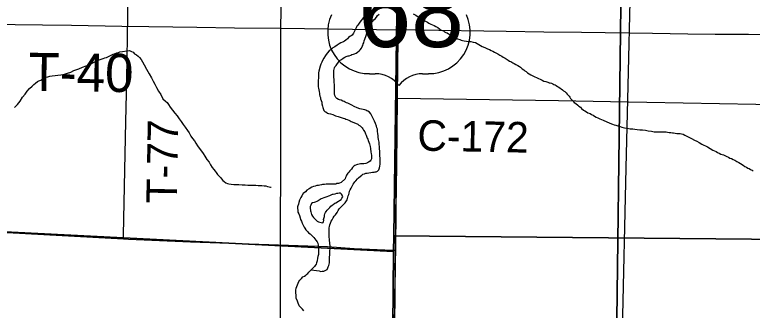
# Model space of a CAD drawing. Extents: x 0 to 68, y 0 to 52.9.
# Drawn here: x 43.122 to 44.57, y 34.125 to 34.705 of the extents above; entities that cross this region are included whole.
import ezdxf

# ---------------------------------------------------------------- set-up
doc = ezdxf.new("R2010")
doc.units = 0
for name, color, linetype in [('Default', 7, 'Continuous'), ('GM_X_County_Road', 7, 'Continuous'), ('GM_X_County_Road_Text', 7, 'Continuous'), ('GM_X_Minor_River', 7, 'Continuous'), ('GM_X_Township', 7, 'Continuous'), ('GM_X_Township_Road', 7, 'Continuous'), ('GM_X_Township_Road_Text', 7, 'Continuous')]:
    doc.layers.add(name, color=color, linetype=linetype)

msp = doc.modelspace()

# ---------------------------------------------------------------- linework, layer by layer
at = {"layer": 'Default'}
for p, q in [((43.8182, 34.5896), (43.8298, 34.5896)), ((43.9227, 34.5896), (43.9343, 34.5896))]:
    msp.add_line(p, q, dxfattribs=at)
for points in [[(43.6416, 32.7683), (43.6433, 34.0176), (43.6445, 34.6783), (43.656, 35.3485), (43.6679, 36.0083), (43.677, 36.4459), (43.686, 36.8454), (43.6904, 37.0468), (43.6959, 37.2899), (43.6976, 37.3155), (43.7023, 37.357), (43.7061, 37.3835), (43.7187, 37.4504), (43.791, 37.8727), (43.7942, 37.8955), (43.7959, 37.9156), (43.7976, 37.9355), (43.7985, 37.9597), (43.7994, 37.991), (43.8015, 38.1232), (43.8073, 38.5411), (43.8097, 38.7192)], [(44.3156, 34.0851), (44.3228, 34.4048), (44.3263, 34.5659), (44.3308, 34.7604), (44.3321, 34.7808), (44.3359, 34.8141), (44.3389, 34.8352), (44.3489, 34.8887), (44.4068, 35.2266), (44.4093, 35.2448), (44.4107, 35.261), (44.4121, 35.2768), (44.4128, 35.2962), (44.4135, 35.3212), (44.4152, 35.427), (44.4199, 35.7613)], [(43.8675, 34.0362), (43.8697, 34.2199), (43.87, 34.2429), (43.871, 34.3249), (43.8721, 34.4102), (43.8734, 34.5417), (43.874, 34.6063), (43.8751, 34.708), (43.8755, 34.7358)]]:
    msp.add_lwpolyline(points, dxfattribs=at)
for points in [[(43.1026, 35.3466), (43.6933, 35.3509), (44.3202, 35.3382), (44.3032, 34.0046), (43.0873, 34.0306), (43.1022, 35.3161)], [(44.3202, 35.3382), (45.6672, 35.3023), (45.6451, 33.9748), (44.3032, 34.0046)], [(42.821, 35.3089), (43.8802, 35.2907), (43.8665, 34.2714), (43.8657, 34.2406), (42.8041, 34.2941)], [(43.8802, 35.2907), (44.9023, 35.2801), (44.8493, 34.2618), (43.8665, 34.2714)], [(42.8041, 34.2941), (43.8657, 34.2406), (43.8561, 33.2057), (43.8558, 33.1813), (42.7855, 33.2374)], [(43.8665, 34.2714), (44.8493, 34.2618), (44.8302, 33.199), (44.3286, 33.2092), (43.8561, 33.2057), (43.8657, 34.2406)]]:
    msp.add_lwpolyline(points, close=True, dxfattribs=at)
for centre, radius, start, end in [((43.8173, 34.6709), 0.0812, 154.8319, 270.6383), ((43.9352, 34.6709), 0.0812, 269.3617, 25.1681), ((43.8298, 34.5316), 0.058, 36.8699, 90), ((43.9227, 34.5316), 0.058, 90, 143.1301)]:
    msp.add_arc(centre, radius, start, end, dxfattribs=at)
at = {"layer": 'GM_X_County_Road'}
for points in [[(43.8734, 34.5417), (44.1895, 34.5367), (44.3255, 34.5342)], [(44.3255, 34.5342), (44.3272, 34.5341), (44.363, 34.5335), (44.6485, 34.5287), (44.9175, 34.5237), (45.1209, 34.519), (45.1669, 34.5181), (45.3604, 34.5135), (45.4008, 34.5128)]]:
    msp.add_lwpolyline(points, dxfattribs=at)
at = {"layer": 'GM_X_Minor_River'}
for points in [[(43.7885, 34.5252), (43.7837, 34.5277), (43.7809, 34.5289), (43.7785, 34.5302), (43.7757, 34.5314), (43.7733, 34.5326), (43.7709, 34.5339), (43.7685, 34.5351), (43.7661, 34.5359), (43.7625, 34.5376), (43.7592, 34.5384), (43.7572, 34.5392), (43.7544, 34.5409), (43.7521, 34.5429), (43.7501, 34.5465), (43.7497, 34.5502), (43.7497, 34.5522), (43.7498, 34.5554), (43.7494, 34.5574), (43.7494, 34.5602), (43.7494, 34.5638), (43.7495, 34.5678), (43.7491, 34.5727), (43.7488, 34.5759), (43.7488, 34.5787), (43.7484, 34.5819), (43.7484, 34.5843), (43.7481, 34.5863), (43.7481, 34.5884), (43.7485, 34.5908), (43.7481, 34.5932), (43.7486, 34.5956), (43.749, 34.5988), (43.7498, 34.6012), (43.7506, 34.6032), (43.7527, 34.606), (43.7588, 34.6144), (43.7608, 34.616), (43.7636, 34.6175), (43.7669, 34.6199), (43.7701, 34.6219), (43.7725, 34.6235), (43.7766, 34.6246), (43.7786, 34.6246), (43.7814, 34.6258), (43.7838, 34.627), (43.7871, 34.6281), (43.7891, 34.6289), (43.7919, 34.6301), (43.7951, 34.6321), (43.798, 34.6345), (43.8, 34.6364), (43.8024, 34.64), (43.8041, 34.6428), (43.8053, 34.6452), (43.8061, 34.648), (43.807, 34.6504), (43.8082, 34.6544), (43.8095, 34.6576), (43.8099, 34.6596), (43.8111, 34.6628), (43.8124, 34.6669), (43.8132, 34.6701), (43.814, 34.6737), (43.8149, 34.6769), (43.8153, 34.6793), (43.8173, 34.6821), (43.8194, 34.6849), (43.8206, 34.6877), (43.823, 34.6909), (43.8251, 34.6928), (43.8271, 34.6952), (43.8295, 34.6976), (43.832, 34.7008), (43.8344, 34.7036), (43.8377, 34.7068)], [(43.8131, 34.7066), (43.8107, 34.7047), (43.8083, 34.7019), (43.8058, 34.6995), (43.8038, 34.6967), (43.8018, 34.6939), (43.7997, 34.6911), (43.7981, 34.6887), (43.7952, 34.6847), (43.7932, 34.6827)], [(43.9044, 34.7073), (43.9092, 34.7044), (43.914, 34.7016), (43.92, 34.6979), (43.9244, 34.6946), (43.9284, 34.6926), (43.932, 34.6909), (43.9352, 34.6889), (43.9388, 34.6872), (43.942, 34.6856), (43.9452, 34.684), (43.9488, 34.6823), (43.9524, 34.6803), (43.956, 34.6778), (43.9592, 34.6754), (43.9636, 34.6737), (43.966, 34.6721), (43.9683, 34.6705), (43.9707, 34.6696), (43.9735, 34.668), (43.9763, 34.6664), (43.9795, 34.6647), (43.9827, 34.6627), (43.9859, 34.6606), (43.9891, 34.659), (43.9915, 34.6582), (43.9955, 34.6565), (43.9983, 34.6553), (44.0012, 34.6548), (44.0044, 34.654), (44.0088, 34.6536), (44.0128, 34.6531), (44.0176, 34.6527), (44.022, 34.6518), (44.0264, 34.6506), (44.0396, 34.6432), (44.0452, 34.6411), (44.05, 34.6387), (44.054, 34.637), (44.0576, 34.6354), (44.0604, 34.6341), (44.0636, 34.6321), (44.0668, 34.6305), (44.0704, 34.6284), (44.0744, 34.626), (44.078, 34.6239), (44.0812, 34.6219), (44.0848, 34.6198), (44.0868, 34.6186), (44.0888, 34.6174), (44.0908, 34.6161), (44.0936, 34.6145), (44.096, 34.6133), (44.098, 34.612), (44.1, 34.6108), (44.1028, 34.6096), (44.106, 34.6075), (44.1096, 34.6059), (44.1128, 34.6039), (44.1152, 34.6022), (44.1184, 34.5994), (44.1212, 34.5973), (44.1232, 34.5953), (44.126, 34.5937), (44.1288, 34.5916), (44.1319, 34.5896), (44.1351, 34.5871), (44.1395, 34.5851), (44.1431, 34.5834), (44.1463, 34.5822), (44.1575, 34.5769), (44.1611, 34.5752), (44.1648, 34.574), (44.1684, 34.5731), (44.1712, 34.5719), (44.1732, 34.5715), (44.1756, 34.5707), (44.1784, 34.5694), (44.1804, 34.5686), (44.1828, 34.5674), (44.1852, 34.5661), (44.1876, 34.5645), (44.19, 34.5629), (44.1928, 34.5612), (44.1948, 34.5596), (44.1972, 34.558), (44.1995, 34.5559), (44.2023, 34.5543), (44.2047, 34.5519)], [(43.7932, 34.6827), (43.792, 34.6799), (43.7908, 34.6771), (43.7895, 34.6747), (43.7883, 34.6719), (43.7867, 34.6695), (43.7842, 34.6655), (43.7822, 34.664), (43.7798, 34.6624), (43.7773, 34.6604), (43.7749, 34.658), (43.7721, 34.6556), (43.7692, 34.6536), (43.7672, 34.6525), (43.7652, 34.6517), (43.7624, 34.6505), (43.7587, 34.6485), (43.7547, 34.6458), (43.7502, 34.6426), (43.7466, 34.6402), (43.7433, 34.6374), (43.7389, 34.6343), (43.7352, 34.6299), (43.732, 34.6255), (43.7287, 34.6203), (43.7262, 34.6155), (43.7246, 34.6123), (43.723, 34.6083), (43.7217, 34.6047), (43.7188, 34.5943), (43.7184, 34.5911), (43.7183, 34.5879), (43.7183, 34.5854), (43.7183, 34.583), (43.7183, 34.5802), (43.7178, 34.5774), (43.7178, 34.5738), (43.7174, 34.5706), (43.7173, 34.567), (43.7177, 34.5638), (43.7181, 34.5609), (43.7188, 34.5581), (43.7192, 34.5549), (43.72, 34.5509), (43.7204, 34.5485), (43.7211, 34.5456), (43.7219, 34.5428), (43.7223, 34.5404), (43.7235, 34.5368), (43.7246, 34.5339), (43.725, 34.5303), (43.7258, 34.5259), (43.7265, 34.5231), (43.7273, 34.5211), (43.7285, 34.5174), (43.7305, 34.5154), (43.7325, 34.5146), (43.7361, 34.5121), (43.7381, 34.5117), (43.7417, 34.5109), (43.7461, 34.5092), (43.7513, 34.5071), (43.7569, 34.5055), (43.7625, 34.5038), (43.7669, 34.5022), (43.7697, 34.5017), (43.7721, 34.5005), (43.7745, 34.4997), (43.7777, 34.4984), (43.7801, 34.4972), (43.7825, 34.496), (43.7845, 34.4951), (43.7954, 34.4906), (43.7977, 34.4886), (43.8001, 34.4869), (43.8037, 34.4833), (43.8053, 34.4813), (43.8069, 34.4784), (43.8093, 34.4752), (43.8104, 34.4716), (43.812, 34.4687), (43.8132, 34.4651), (43.814, 34.4631), (43.8148, 34.4611), (43.8159, 34.4582), (43.8171, 34.455), (43.8183, 34.4518), (43.8191, 34.449), (43.8194, 34.4466), (43.8202, 34.4425), (43.8213, 34.4357), (43.8217, 34.4325), (43.8221, 34.4292), (43.822, 34.4256), (43.822, 34.4224), (43.8212, 34.42), (43.8196, 34.4176), (43.8167, 34.4156), (43.8147, 34.4144), (43.8111, 34.4133), (43.8074, 34.4125)], [(43.1209, 34.5229), (43.127, 34.5294), (43.1321, 34.5358), (43.1367, 34.5438), (43.1422, 34.5493), (43.1458, 34.5553), (43.1509, 34.5608), (43.1555, 34.5652), (43.159, 34.5682), (43.1625, 34.5712), (43.1661, 34.5742), (43.1691, 34.5756), (43.1727, 34.5771), (43.1787, 34.5806), (43.1828, 34.5825), (43.1868, 34.5835), (43.1908, 34.5845), (43.1953, 34.5854), (43.2009, 34.5859), (43.2064, 34.5868), (43.2119, 34.5873), (43.219, 34.5887), (43.2255, 34.5906), (43.2316, 34.5926), (43.2377, 34.596), (43.2472, 34.5994), (43.2548, 34.6024), (43.2619, 34.6053), (43.2689, 34.6078), (43.275, 34.6112), (43.2826, 34.6147), (43.2891, 34.6176), (43.2952, 34.6195), (43.2987, 34.6205), (43.3017, 34.6215), (43.3042, 34.623), (43.3073, 34.6239), (43.3123, 34.6264), (43.3148, 34.6279), (43.3174, 34.6289), (43.3219, 34.6303), (43.3254, 34.6313), (43.3279, 34.6323), (43.333, 34.6332), (43.3415, 34.6346), (43.3471, 34.6351), (43.3506, 34.6335), (43.3541, 34.632), (43.3571, 34.6289), (43.361, 34.6264), (43.364, 34.6239), (43.3665, 34.6213), (43.37, 34.6173), (43.3725, 34.6132), (43.3759, 34.6072), (43.3804, 34.5986), (43.3853, 34.589), (43.3902, 34.5814), (43.3937, 34.5748), (43.3967, 34.5688), (43.4001, 34.5622), (43.4041, 34.5551), (43.4085, 34.5485), (43.4125, 34.5405), (43.4174, 34.5359), (43.4209, 34.5328), (43.4234, 34.5293), (43.4269, 34.5237), (43.4313, 34.5177), (43.4363, 34.5121), (43.4403, 34.5065), (43.4447, 34.5009), (43.4487, 34.4954), (43.4521, 34.4898), (43.4561, 34.4843), (43.4611, 34.4782), (43.464, 34.4731), (43.4675, 34.4671)], [(44.2047, 34.5519), (44.2067, 34.5494), (44.2087, 34.5474), (44.2107, 34.5454), (44.2119, 34.5434), (44.2135, 34.5409), (44.2159, 34.5385), (44.2178, 34.5361), (44.2206, 34.5332), (44.2234, 34.5308), (44.2274, 34.5275), (44.2298, 34.5259), (44.2326, 34.5238), (44.235, 34.521), (44.2386, 34.5182), (44.2414, 34.5165), (44.2446, 34.5149), (44.2474, 34.5128), (44.2518, 34.5112), (44.2546, 34.5096), (44.2578, 34.5079), (44.2606, 34.5059), (44.2634, 34.5042), (44.267, 34.5026), (44.2706, 34.5009), (44.2742, 34.4997), (44.2774, 34.4985), (44.2906, 34.4927), (44.2954, 34.4906), (44.299, 34.4894), (44.3022, 34.4886), (44.3042, 34.4881), (44.3078, 34.4865), (44.3106, 34.4857), (44.3142, 34.4844), (44.319, 34.4832), (44.3246, 34.4823), (44.3302, 34.481), (44.3359, 34.481), (44.3395, 34.4805), (44.3439, 34.4801), (44.3495, 34.4796), (44.3547, 34.4792), (44.3604, 34.4787), (44.366, 34.4775), (44.372, 34.4766), (44.3772, 34.4757), (44.3816, 34.4753), (44.3857, 34.4752), (44.3901, 34.4752), (44.3929, 34.4756), (44.3953, 34.4755), (44.3977, 34.4751), (44.4009, 34.4751), (44.4037, 34.4746), (44.407, 34.4742), (44.4102, 34.4738), (44.4134, 34.4737), (44.4158, 34.4733), (44.419, 34.4729), (44.4222, 34.4724), (44.4258, 34.4724), (44.4286, 34.472), (44.4314, 34.4715), (44.4343, 34.4707), (44.4375, 34.4691), (44.4414, 34.467), (44.4458, 34.4646), (44.451, 34.4621), (44.4566, 34.4592), (44.4614, 34.4568), (44.4658, 34.4547), (44.4714, 34.4514), (44.475, 34.4494), (44.4786, 34.4477), (44.4822, 34.4457), (44.4926, 34.4396), (44.4962, 34.4379), (44.4994, 34.4367), (44.5022, 34.435), (44.5054, 34.4338), (44.5086, 34.4318), (44.5134, 34.4301), (44.5166, 34.4289), (44.5202, 34.4272), (44.5234, 34.4256), (44.5262, 34.4239), (44.5294, 34.4227), (44.5326, 34.4211), (44.5358, 34.4194), (44.5398, 34.417), (44.5438, 34.4149), (44.5474, 34.4129), (44.5522, 34.41), (44.5558, 34.4076), (44.5586, 34.4059), (44.5614, 34.4043), (44.5642, 34.4031), (44.567, 34.4014), (44.5698, 34.4002), (44.5718, 34.399)], [(43.7396, 34.2179), (43.7401, 34.2219), (43.7401, 34.2255), (43.7401, 34.2292), (43.7402, 34.2336), (43.7406, 34.2376), (43.7407, 34.2412), (43.7411, 34.246), (43.7411, 34.2508), (43.7401, 34.2625), (43.7393, 34.2706), (43.739, 34.2766), (43.739, 34.2802), (43.7391, 34.2834), (43.7391, 34.2866), (43.7399, 34.2894), (43.7408, 34.293), (43.742, 34.2962), (43.7432, 34.2999), (43.7453, 34.3026), (43.7469, 34.3066), (43.749, 34.3094), (43.7514, 34.3126), (43.7547, 34.3166), (43.7571, 34.3206), (43.7591, 34.3238), (43.7608, 34.3262), (43.7628, 34.3282), (43.7665, 34.3322), (43.7685, 34.3342), (43.7705, 34.3361), (43.7717, 34.3381), (43.773, 34.3401), (43.7742, 34.3421), (43.775, 34.3445), (43.7759, 34.3473), (43.7767, 34.3497), (43.7775, 34.3521), (43.7783, 34.3549), (43.7792, 34.3586), (43.7804, 34.3614), (43.7821, 34.3646), (43.7837, 34.3674), (43.7849, 34.3697), (43.7866, 34.3725), (43.7882, 34.3749), (43.7898, 34.3769), (43.7914, 34.3789), (43.7947, 34.3833), (43.7971, 34.3849), (43.8004, 34.3881), (43.8032, 34.3905), (43.8052, 34.392), (43.8085, 34.3932), (43.8109, 34.394), (43.8137, 34.3944), (43.8246, 34.3959), (43.8278, 34.3962), (43.8298, 34.3966), (43.8318, 34.397), (43.8342, 34.3978), (43.8367, 34.401), (43.8379, 34.4046), (43.8384, 34.4082), (43.8392, 34.4118), (43.8392, 34.4138), (43.8392, 34.4162), (43.8393, 34.419), (43.8393, 34.4214), (43.8393, 34.4238), (43.839, 34.4283), (43.839, 34.4311), (43.839, 34.4331), (43.8386, 34.4371), (43.8383, 34.4419), (43.8379, 34.4468), (43.8376, 34.4508), (43.8372, 34.4548), (43.8368, 34.4576), (43.8361, 34.46), (43.8357, 34.4649), (43.8353, 34.4685), (43.835, 34.4717), (43.8342, 34.4765), (43.8338, 34.4806), (43.8331, 34.483), (43.8319, 34.4862), (43.8299, 34.4915), (43.8284, 34.4963), (43.8264, 34.5003), (43.8244, 34.504), (43.8225, 34.5084), (43.8209, 34.5108), (43.8181, 34.5137), (43.8153, 34.5161), (43.8133, 34.5169), (43.8113, 34.5178), (43.8093, 34.5186), (43.7997, 34.5207), (43.7941, 34.5228), (43.7885, 34.5252)], [(43.4675, 34.4671), (43.471, 34.462), (43.4744, 34.4574), (43.4774, 34.4529), (43.4804, 34.4478), (43.4918, 34.4326), (43.4952, 34.4276), (43.4987, 34.421), (43.5032, 34.4159), (43.5061, 34.4104), (43.5096, 34.4053), (43.5126, 34.4013), (43.5151, 34.3982), (43.517, 34.3952), (43.52, 34.3917), (43.5225, 34.3891), (43.526, 34.3856), (43.528, 34.383), (43.5304, 34.38), (43.5329, 34.3775), (43.5364, 34.3749), (43.5394, 34.3739), (43.5424, 34.3733), (43.547, 34.3728), (43.552, 34.3722), (43.5575, 34.3722), (43.562, 34.3716), (43.568, 34.3711), (43.5741, 34.371), (43.5796, 34.3704), (43.5856, 34.3704), (43.5906, 34.3703), (43.5952, 34.3703), (43.5997, 34.3702), (43.6037, 34.3702), (43.6072, 34.3697), (43.6117, 34.3696), (43.6148, 34.3691), (43.6183, 34.368), (43.6213, 34.3675), (43.6238, 34.367), (43.6253, 34.367)], [(43.8074, 34.4125), (43.8038, 34.4122), (43.8006, 34.4122), (43.7978, 34.4118), (43.795, 34.411), (43.7926, 34.4103), (43.7897, 34.4091), (43.7877, 34.4079), (43.7853, 34.4055), (43.7828, 34.4023), (43.7796, 34.3987), (43.7775, 34.3959), (43.7759, 34.394), (43.7735, 34.39), (43.7726, 34.388), (43.7714, 34.3856), (43.7706, 34.3832), (43.7625, 34.376), (43.7597, 34.3748), (43.7576, 34.3741), (43.7544, 34.3737), (43.7524, 34.3729), (43.7496, 34.3725), (43.746, 34.3726), (43.7427, 34.3726), (43.7391, 34.3726), (43.7359, 34.3727), (43.7331, 34.3727), (43.7303, 34.3719), (43.7263, 34.3716), (43.7238, 34.3712), (43.721, 34.3708), (43.7182, 34.37), (43.715, 34.3697), (43.7118, 34.3689), (43.7085, 34.3681), (43.7049, 34.3666), (43.6996, 34.3634), (43.6952, 34.3606), (43.6928, 34.3574), (43.6883, 34.3543), (43.6854, 34.3499), (43.6838, 34.3463), (43.6822, 34.3435), (43.6809, 34.3411), (43.6797, 34.3367), (43.6789, 34.3335), (43.6776, 34.3303), (43.6772, 34.3279), (43.6768, 34.3251), (43.6775, 34.3218), (43.6779, 34.3174), (43.6795, 34.3146), (43.6806, 34.311), (43.6822, 34.3065), (43.683, 34.3029), (43.6846, 34.2997), (43.6861, 34.296), (43.6873, 34.2932), (43.6885, 34.2908), (43.6901, 34.2883), (43.6917, 34.2859), (43.6936, 34.2827), (43.6964, 34.2798), (43.6988, 34.277), (43.7016, 34.275), (43.7092, 34.2677), (43.7111, 34.2652), (43.7131, 34.2628), (43.7155, 34.2596), (43.7167, 34.2567), (43.7175, 34.2527), (43.7182, 34.2487), (43.7182, 34.2463), (43.7182, 34.2443), (43.7181, 34.2402), (43.7181, 34.2374), (43.7181, 34.2346), (43.7172, 34.2302), (43.7164, 34.2274), (43.7155, 34.2222), (43.7143, 34.2182), (43.7139, 34.2154), (43.7118, 34.2126), (43.7102, 34.2106), (43.7086, 34.2086), (43.7065, 34.2066), (43.7041, 34.2042)], [(43.7468, 34.3328), (43.75, 34.3351), (43.7524, 34.3359), (43.7573, 34.3395), (43.7597, 34.3407), (43.7626, 34.3427), (43.7642, 34.345), (43.7658, 34.3478), (43.7646, 34.3507), (43.7631, 34.3531), (43.7615, 34.3551), (43.7591, 34.3551), (43.7562, 34.3544), (43.7534, 34.354), (43.7506, 34.3532), (43.747, 34.3525), (43.745, 34.3521), (43.7425, 34.3509), (43.7401, 34.3497), (43.7377, 34.3489), (43.7345, 34.3478), (43.7304, 34.3466), (43.7236, 34.3435), (43.7216, 34.3427), (43.7175, 34.3399), (43.7151, 34.3387), (43.7119, 34.3372), (43.7098, 34.3364), (43.7066, 34.3356), (43.7046, 34.3344)], [(43.7046, 34.3344), (43.7029, 34.3312), (43.7021, 34.3288), (43.7017, 34.3264), (43.7024, 34.3204), (43.7032, 34.3184), (43.7036, 34.3159), (43.7044, 34.3127), (43.7064, 34.3099), (43.7087, 34.307), (43.7123, 34.3034), (43.7155, 34.3001), (43.7183, 34.2985), (43.7207, 34.2977), (43.7235, 34.2972), (43.7267, 34.2964), (43.728, 34.2984), (43.7284, 34.3012), (43.728, 34.3032), (43.7288, 34.3052), (43.7297, 34.3088), (43.7301, 34.3116), (43.7309, 34.314), (43.7322, 34.3168), (43.733, 34.3188), (43.7354, 34.3216), (43.7374, 34.3232), (43.7403, 34.3268), (43.7427, 34.3292), (43.7448, 34.3316), (43.7468, 34.3328)], [(43.7041, 34.2042), (43.7198, 34.2024), (43.723, 34.2012), (43.7254, 34.2016), (43.729, 34.2019), (43.731, 34.2027), (43.7351, 34.2051), (43.7363, 34.2079), (43.7375, 34.2099), (43.7384, 34.2127), (43.7392, 34.2155), (43.7396, 34.2179)], [(43.6757, 34.1716), (43.6769, 34.1748), (43.6781, 34.178), (43.6798, 34.1812), (43.6814, 34.1839), (43.6847, 34.1875), (43.6875, 34.1903), (43.6907, 34.1919), (43.6932, 34.1939), (43.6952, 34.1955), (43.6972, 34.197), (43.6992, 34.1994), (43.7021, 34.2022), (43.7041, 34.2042)], [(43.6893, 34.124), (43.6865, 34.1268), (43.6837, 34.1305), (43.6805, 34.1333), (43.6797, 34.1353), (43.6786, 34.1386), (43.677, 34.1426), (43.6742, 34.1487), (43.6743, 34.1511), (43.6743, 34.1551), (43.6739, 34.1583), (43.6739, 34.1607), (43.674, 34.1643), (43.6744, 34.1683), (43.6757, 34.1716)]]:
    msp.add_lwpolyline(points, dxfattribs=at)
at = {"layer": 'GM_X_Township'}
msp.add_lwpolyline([(43.8255, 31.1431), (43.8412, 32.1252), (43.8416, 32.1514), (43.848, 32.6506), (43.8484, 32.6776), (43.8577, 33.1798), (43.8583, 33.2049), (43.8631, 33.7395), (43.8693, 34.2426), (43.8728, 34.5425), (43.8742, 34.7352), (43.8773, 34.8686), (43.8737, 34.9229), (43.874, 34.9402), (43.8796, 35.1936), (43.8797, 35.2152), (43.8798, 35.2893), (44.0257, 35.2866), (44.0303, 35.2868), (44.6712, 35.2829), (45.1961, 35.2737), (45.9849, 35.2547)], dxfattribs=at)
at = {"layer": 'GM_X_Township_Road'}
for points in [[(43.3435, 34.7043), (43.3457, 34.8534), (43.3476, 34.9388), (43.3486, 35.0012), (43.3503, 35.1096), (43.3531, 35.2935), (43.3532, 35.2977)], [(43.3354, 34.2651), (43.3355, 34.2721), (43.3401, 34.4954), (43.3415, 34.5775), (43.3435, 34.7043)], [(43.1061, 34.6871), (43.1226, 34.6864), (43.1759, 34.6857), (43.2333, 34.6848), (43.3318, 34.683), (43.3851, 34.6824), (43.4795, 34.6807), (43.5534, 34.68), (43.6436, 34.6788), (43.8324, 34.6764), (43.9104, 34.6757), (44.0868, 34.6732), (44.1607, 34.6721), (44.2345, 34.6712), (44.3741, 34.6693), (44.4438, 34.6679), (44.4972, 34.6675), (44.5629, 34.667), (44.6654, 34.6647)], [(42.806, 34.2933), (42.8145, 34.2929), (42.8894, 34.2893), (43.3354, 34.2651)], [(43.3354, 34.2651), (43.3452, 34.2645), (43.4667, 34.2596), (43.7358, 34.2498), (43.7882, 34.246), (43.8636, 34.2431), (43.87, 34.2429)]]:
    msp.add_lwpolyline(points, dxfattribs=at)

# ---------------------------------------------------------------- texts
at = {"layer": 'Default'}
msp.add_text('68', height=0.13922, dxfattribs=at).set_placement((43.7966, 34.6419))
at = {"layer": 'GM_X_County_Road_Text'}
msp.add_text('C-172', height=0.06, rotation=358.8979, dxfattribs=at).set_placement((43.9121, 34.4386))
at = {"layer": 'GM_X_Township_Road_Text'}
for s, height, rotation, p in [('T-40', 0.075, 359.2931, (43.1482, 34.5558)), ('T-77', 0.06, 88.9383, (43.4399, 34.3341))]:
    msp.add_text(s, height=height, rotation=rotation, dxfattribs=at).set_placement(p)

doc.saveas('drawing.dxf')
